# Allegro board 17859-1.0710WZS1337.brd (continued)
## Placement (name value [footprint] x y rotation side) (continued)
C6306  SCD047U25V2KX-4-GP  [C402H22]  219.71 4.17 90 top
C6307  SCD1U16V2KX-3DLGP  [C402H22]  219.71 3.39 90 top
C6308  SCD047U25V2KX-4-GP  [C402H22]  217.6 22.43 180 top
C6311  SCD22U10V2KX-2-GP  [C402H22]  204.54 21.01 90 bottom
C6312  SCD22U10V2KX-2-GP  [C402H22]  204.54 21.8 90 bottom
C6313  SCD22U10V2KX-2-GP  [C402H22]  205.76 17.78 90 bottom
C6314  SCD22U10V2KX-2-GP  [C402H22]  205.76 18.54 90 bottom
C6315  SCD22U10V2KX-2-GP  [C402H22]  205.32 15.49 90 bottom
C6316  SCD22U10V2KX-2-GP  [C402H22]  205.32 16.25 90 bottom
C6321  SC22U6D3V3MX-1-DL-GP  [C603H40]  216.28 19.18 270 top
C6322  SC22U6D3V3MX-1-DL-GP  [C603H40]  217.06 7.42 180 top
C6401  SCD1U16V2KX-3DLGP  [C402H22]  52.95 54.13 90 top
C6402  SCD1U16V2KX-3GP  [C402H22]  41.09 54.92 0 top
C6501  SCD1U16V2KX-3GP  [C402H22]  97.61 14.23 180 top
C6502  SCD1U16V2KX-3GP  [C402H22]  100.68 14.46 180 top
C6503  SCD1U16V2KX-3GP  [C402H22]  173.88 14.56 90 top
C6504  SCD1U16V2KX-3GP  [C402H22]  177.39 6.58 90 top
C7003  SCD1U25V2KX-1-DL-GP  [C402H22]  167.43 55.58 90 top
C7004  SC10U6D3V3MX-GP  [C603H38]  167.43 54.43 90 top
C7219  SC1U25V3KX-1-DLGP  [C603H36]  71.42 102.52 90 top
C7220  SC220P50V2KX-3GP  [C402H22]  72.38 105.03 0 top
C7221  SC220P50V2KX-3GP  [C402H22]  71.24 104.73 90 top
C7222  SC22U6D3V3MX-1-DL-GP  [C603H40]  67.2 94.19 0 top
C7223  SCD22U10V2KX-L1-GP  [C402H22]  74.8 98.58 0 bottom
C7224  SC2D2U10V3KX-L-GP  [C603H36]  86.83 101.52 90 bottom
C7225  SC1U10V2KX-L1-GP  [C402H22]  83.31 101.78 90 top
C7226  SC2D2U10V3KX-L-GP  [C603H36]  79.6 93.4 180 top
C7227  SC22U6D3V3MX-1-DL-GP  [C603H40]  68.47 94.19 0 top
C7228  SC10U6D3V3MX-L-GP  [C603H38]  83.74 99.98 90 top
C7229  SC10U6D3V3MX-L-GP  [C603H38]  86.91 94.49 270 top
C7230  SC2D2U10V3KX-L-GP  [C603H36]  84.32 98.2 0 top
C7231  SC22U6D3V3MX-1-DL-GP  [C603H40]  69.74 94.19 0 top
C7232  SC22U6D3V3MX-1-DL-GP  [C603H40]  70.94 94.19 0 top
C7244  SCD1U16V2KX-3DLGP  [C402H22]  83.56 100.97 90 top
C7301  SCD1U16V2KX-3DLGP  [C402H22]  31.85 71.45 90 top
C7302  SCD1U16V2KX-3DLGP  [C402H22]  31.85 72.27 90 top
C7303  SCD1U16V2KX-3DLGP  [C402H22]  23.84 67.39 180 top
C7304  SCD1U16V2KX-3DLGP  [C402H22]  23.08 67.39 180 top
C7305  SCD1U16V2KX-3DLGP  [C402H22]  21.08 66.96 180 top
C7306  SCD1U16V2KX-3DLGP  [C402H22]  20.31 66.96 180 top
C7307  SCD1U16V2KX-3DLGP  [C402H22]  26.61 66.78 180 top
C7308  SCD1U16V2KX-3DLGP  [C402H22]  28.39 65.97 180 top
C7309  SCD1U16V2KX-3DLGP  [C402H22]  27.63 65.97 180 top
C7310  SCD1U16V2KX-3DLGP  [C402H22]  30.6 65.56 180 top
C7311  SCD1U16V2KX-3DLGP  [C402H22]  29.84 65.56 180 top
C7312  SCD1U16V2KX-3DLGP  [C402H22]  24.07 65.69 180 top
C7313  SCD1U16V2KX-3DLGP  [C402H22]  24.84 65.69 180 top
C7314  SCD1U16V2KX-3DLGP  [C402H22]  25.85 66.78 180 top
C7315  SCD1U16V2KX-3DLGP  [C402H22]  29.25 69.09 0 bottom
C7316  SCD1U16V2KX-3DLGP  [C402H22]  29.43 71.33 180 bottom
C7317  SCD1U16V2KX-3DLGP  [C402H22]  18.51 71.05 270 top
C7318  SCD1U16V2KX-3DLGP  [C402H22]  30.19 71.33 180 bottom
C7319  SC10U6D3V3MX-DL-GP  [C603H36]  24.4 70.61 270 bottom
C7321  SCD1U16V2KX-3DLGP  [C402H22]  25.6 74.6 180 top
C7322  SCD1U16V2KX-3DLGP  [C402H22]  26.36 74.6 180 top
C7323  SCD1U16V2KX-3DLGP  [C402H22]  27.12 74.6 180 top
C7324  SCD1U16V2KX-3DLGP  [C402H22]  27.88 74.6 180 top
C7325  SCD1U25V2KX-1-DL-GP  [C402H22]  10.38 85.75 180 bottom
C7326  SCD1U25V2KX-1-DL-GP  [C402H22]  10.92 90.93 180 bottom
C7327  SCD1U25V2KX-1-DL-GP  [C402H22]  13.56 91.75 90 top
C7328  SCD1U25V2KX-1-DL-GP  [C402H22]  13.56 90.99 90 top
C7329  SC1U25V3KX-1-DLGP  [C603H36]  12.87 85.19 180 bottom
C7330  SC10U25V5KX-DL-GP  [C805H58]  13.28 91.47 180 bottom
C7331  SCD1U16V2KX-3DLGP  [C402H22]  28.11 77.07 180 top
C7332  SCD1U16V2KX-3DLGP  [C402H22]  27.33 77.07 180 top
C7333  SCD1U16V2KX-3DLGP  [C402H22]  24.63 76.41 180 top
C7334  SCD1U16V2KX-3DLGP  [C402H22]  25.39 76.41 180 top
C7401  SC1500P50V2KX-2GP  [C402H22]  24.58 85.78 270 bottom
C7601  SCD22U10V2KX-1GP  [C402H22]  161.56 80.7 90 top
C7602  SCD22U10V2KX-1GP  [C402H22]  161.56 79.91 90 top
C7603  SCD22U10V2KX-1GP  [C402H22]  161.57 82.33 90 top
C7604  SCD22U10V2KX-1GP  [C402H22]  161.57 81.56 90 top
C7605  SCD22U10V2KX-1GP  [C402H22]  158.65 83.74 90 top
C7606  SCD22U10V2KX-1GP  [C402H22]  158.65 84.59 90 top
C7607  SCD22U10V2KX-1GP  [C402H22]  159.3 82.19 90 top
C7608  SCD22U10V2KX-1GP  [C402H22]  159.3 82.96 90 top
C7610  SC4D7U6D3V3KX-DLGP  [C603H36]  183.28 106.91 0 bottom
C7611  SC4D7U6D3V3KX-DLGP  [C603H36]  186.38 104.57 270 bottom
C7612  SC1U10V2KX-1GP  [C402H22]  180.59 106.43 0 bottom
C7613  SC4D7U6D3V3KX-DLGP  [C603H36]  186.38 105.84 270 bottom
C7614  SC1U10V2KX-1GP  [C402H22]  178.12 85.42 225 top
C7615  SC4D7U6D3V3KX-DLGP  [C603H36]  177.79 97.79 0 bottom
C7616  SCD1U16V2KX-3GP  [C402H22]  176.98 85.45 45 top
C7620  SC4D7U6D3V3KX-DLGP  [C603H36]  178.18 89.82 225 top
C7621  SC4D7U6D3V3KX-DLGP  [C603H36]  180.49 92.97 225 top
C7622  SC1U10V2KX-1GP  [C402H22]  182.34 91.11 135 top
C7623  SC10U6D3V3MX-GP  [C603H38]  186.38 103.3 270 bottom
C7624  SC4D7U6D3V3KX-DLGP  [C603H36]  179.22 99.14 0 bottom
C7625  SC10U6D3V3MX-GP  [C603H38]  184.55 106.91 0 bottom
C7626  SC22U6D3V3MX-1-DL-GP  [C603H40]  182.01 106.91 0 bottom
C7627  SC10U6D3V3MX-GP  [C603H38]  178.66 91.14 225 top
C7628  SC22U6D3V3MX-1-DL-GP  [C603H40]  179.11 87.25 45 top
C7629  SC10U6D3V3MX-GP  [C603H38]  179.57 92.05 225 top
C7630  SC1U10V2KX-1GP  [C402H22]  181.78 91.68 135 top
C7631  SC1U10V2KX-1GP  [C402H22]  180.97 93.96 225 top
C7632  SCD1U16V2KX-3GP  [C402H22]  176.4 93.65 225 top
C7633  SC1U10V2KX-1GP  [C402H22]  176.96 94.21 225 top
C7634  SC4D7U6D3V3KX-DLGP  [C603H36]  176.91 92.1 315 top
C7801  SCD1U16V2KX-3GP  [C402H22]  187.17 95.14 225 top
C7802  SCD1U16V2KX-3GP  [C402H22]  187.7 95.69 225 top
C7805  SCD1U16V2KX-3GP  [C402H22]  186.3 88.72 315 top
C7806  SCD1U16V2KX-3GP  [C402H22]  188.31 82.15 270 top
C7807  SC1U25V3KX-1-DLGP  [C603H36]  208.1 86.21 0 bottom
C7808  SCD1U16V2KX-3GP  [C402H22]  188.31 81.37 270 top
C7809  SCD1U16V2KX-3GP  [C402H22]  197.33 74.12 45 top
C7813  SC4D7U6D3V3KX-DLGP  [C603H36]  205.53 86.21 180 bottom
C7814  SC4D7U6D3V3KX-DLGP  [C603H36]  206.8 86.21 180 bottom
C7817  SC10U6D3V3MX-GP  [C603H38]  220.54 94.77 270 bottom
C7818  SC22U6D3V3MX-1-DL-GP  [C603H40]  184.73 89.77 315 top
C7820  SC22U6D3V3MX-1-DL-GP  [C603H40]  220.54 97.36 270 bottom
C7825  SC1U25V3KX-1-DLGP  [C603H36]  220.54 96.09 90 bottom
C7826  SC1U25V3KX-1-DLGP  [C603H36]  220.47 102.95 90 bottom
C7827  SC1U25V3KX-1-DLGP  [C603H36]  201.7 104.47 180 bottom
C7828  SC1U25V3KX-1-DLGP  [C603H36]  220.46 101.67 90 bottom
C7829  SC1U25V3KX-1-DLGP  [C603H36]  203 104.47 180 bottom
C7830  SC1U25V3KX-1-DLGP  [C603H36]  220.54 93.47 90 bottom
C7831  SC1U25V3KX-1-DLGP  [C603H36]  220.29 96.34 270 top
C7832  SC22U6D3V3MX-1-DL-GP  [C603H40]  206.83 83.26 0 bottom
C7833  SC22U6D3V3MX-1-DL-GP  [C603H40]  205.56 83.26 0 bottom
C7834  SC10U6D3V3MX-GP  [C603H38]  213.14 86.44 180 bottom
C7835  SC10U6D3V3MX-GP  [C603H38]  204.37 104.47 0 bottom
C7903  SCD1U16V2KX-3GP  [C402H22]  168.02 80.83 225 bottom
C7906  SCD1U16V2KX-3GP  [C402H22]  183.66 79.17 225 top
C7907  SC18P50V2JN-1-GP  [C402H22]  185.34 63.45 90 bottom
C7908  SC18P50V2JN-1-GP  [C402H22]  183.86 63.45 270 bottom
C7909  SCD22U10V2KX-L1-GP  [C402H22]  188.06 60.71 180 bottom
C7934  SC10U6D3V3MX-GP  [C603H38]  178.61 95.1 315 top
C7935  SC22U6D3V3MX-1-DL-GP  [C603H40]  179.98 84.56 225 top
C7936  SCD1U16V2KX-3GP  [C402H22]  181.73 81.82 135 top
C7937  SCD1U16V2KX-3GP  [C402H22]  180.44 82.15 225 top
C7938  SC22U6D3V3MX-1-DL-GP  [C603H40]  183.92 94.11 225 top
C7939  SC22U6D3V3MX-1-DL-GP  [C603H40]  180.77 95.61 45 top
C8001  SC4D7U6D3V3KX-DLGP  [C603H36]  150.84 106.68 180 top
C8002  SC4D7U6D3V3KX-DLGP  [C603H36]  149.55 106.68 180 top
C8003  SC4D7U6D3V3KX-DLGP  [C603H36]  177.06 72.06 45 bottom
C8004  SC4D7U6D3V3KX-DLGP  [C603H36]  184.83 80.62 225 top
C8008  SC4D7U6D3V3KX-DLGP  [C603H36]  151.68 96.47 90 top
C8009  SC4D7U6D3V3KX-DLGP  [C603H36]  151.68 97.74 90 top
C8010  SC22U6D3V3MX-1-DL-GP  [C603H40]  151.68 99.01 90 top
C8011  SC1U10V2KX-1GP  [C402H22]  185.09 83.34 45 top
C8012  SC1U10V2KX-1GP  [C402H22]  185.42 87.45 135 top
C8013  SC1U10V2KX-1GP  [C402H22]  187.85 87.71 135 top
C8014  SC1U10V2KX-1GP  [C402H22]  184.86 87.99 135 top
C8015  SC4D7U6D3V3KX-GP  [C603H36]  160.6 88.47 135 bottom
C8016  SC4D7U6D3V3KX-GP  [C603H36]  172.26 75.75 135 bottom
C8017  SC22U6D3V3MX-1-DL-GP  [C603H40]  168.9 79.1 135 bottom
C8018  SC1U10V2KX-1GP  [C402H22]  183 83.62 315 top
C8019  SC4D7U6D3V3KX-DLGP  [C603H36]  170.58 77.42 135 bottom
C8020  SC4D7U6D3V3KX-DLGP  [C603H36]  169.74 78.26 135 bottom
C8021  SC4D7U6D3V3KX-DLGP  [C603H36]  186.1 85.63 45 top
C8022  SC4D7U6D3V3KX-DLGP  [C603H36]  185.19 84.71 45 top
C8023  SC4D7U6D3V3KX-DLGP  [C603H36]  182.77 89.11 225 top
C8024  SC4D7U6D3V3KX-DLGP  [C603H36]  181.86 88.19 225 top
C8025  SC4D7U6D3V3KX-DLGP  [C603H36]  180.95 87.28 225 top
C8026  SC4D7U6D3V3KX-DLGP  [C603H36]  171.42 76.58 135 bottom
C8028  SC1U10V2KX-1GP  [C402H22]  178.12 71.68 315 top
C8029  SCD1U16V2KX-3GP  [C402H22]  177.57 72.24 315 top
C8030  SC4D7U6D3V3KX-DLGP  [C603H36]  187.02 86.54 45 top
C8031  SC4D7U6D3V3KX-DLGP  [C603H36]  151.68 100.28 90 top
C8032  SC4D7U6D3V3KX-DLGP  [C603H36]  151.68 101.55 90 top
C8034  SCD1U16V2KX-3GP  [C402H22]  177.01 72.8 315 top
C8035  SCD1U16V2KX-3GP  [C402H22]  184.35 79.66 225 top
C8036  SC1U10V2KX-1GP  [C402H22]  187.12 80.9 45 top
C8037  SCD1U16V2KX-3DLGP  [C402H22]  187.5 76.66 315 top
C8038  SC10U6D3V3MX-DL-GP  [C603H36]  173.1 74.91 135 bottom
C8039  SC10U6D3V3MX-DL-GP  [C603H36]  166.31 79.56 90 bottom
C8040  SC10U6D3V3MX-DL-GP  [C603H36]  174.77 73.23 135 bottom
C8041  SC10U6D3V3MX-DL-GP  [C603H36]  173.93 74.07 135 bottom
C8042  SC10U6D3V3MX-DL-GP  [C603H36]  163.47 87.68 135 bottom
C8043  SC10U6D3V3MX-DL-GP  [C603H36]  161.51 87.56 135 bottom
C8044  SC10U6D3V3MX-DL-GP  [C603H36]  165.7 88.04 315 bottom
C8045  SC10U6D3V3MX-DL-GP  [C603H36]  163.6 85.93 135 bottom
C8046  SC10U6D3V3MX-DL-GP  [C603H36]  164.51 85.02 135 bottom
C8047  SC22U6D3V3MX-1-DL-GP  [C603H40]  186.51 78.95 225 top
C8048  SC4D7U6D3V3KX-GP  [C603H36]  185.24 77.73 225 top
C8089  SCD1U16V2KX-3GP  [C402H22]  186.56 80.34 45 top
C8101  SC1U10V2KX-L1-GP  [C402H22]  220.32 71.3 90 top
C8102  SC1U10V2KX-L1-GP  [C402H22]  220.32 76.51 90 top
C8103  SC1U10V2KX-L1-GP  [C402H22]  220.32 72.06 90 top
C8104  SC1U10V2KX-L1-GP  [C402H22]  206.22 64.95 90 bottom
C8105  SC1U10V2KX-L1-GP  [C402H22]  220.32 72.16 270 bottom
C8106  SC1U10V2KX-L1-GP  [C402H22]  220.32 74.53 270 bottom
C8107  SC1U10V2KX-L1-GP  [C402H22]  220.44 71.38 270 bottom
C8108  SC1U10V2KX-L1-GP  [C402H22]  220.32 73.64 90 top
C8109  SC1U10V2KX-L1-GP  [C402H22]  220.32 75.72 90 top
C8110  SC1U10V2KX-L1-GP  [C402H22]  206.22 65.71 90 bottom
C8111  SC10U6D3V3MX-GP  [C603H38]  220.32 73.33 270 bottom
C8112  SC10U6D3V3MX-GP  [C603H38]  201.03 77.29 90 bottom
C8113  SC10U6D3V3MX-GP  [C603H38]  202.92 66.2 180 bottom
C8114  SC10U6D3V3MX-GP  [C603H38]  204.08 66.2 180 bottom
C8115  SC1U10V2KX-L1-GP  [C402H22]  220.44 100.59 270 bottom
C8116  SC1U10V2KX-L1-GP  [C402H22]  220.32 72.85 90 top
C8117  SC1U10V2KX-L1-GP  [C402H22]  220.36 77.88 270 bottom
C8118  SC1U10V2KX-L1-GP  [C402H22]  213.63 66.83 0 top
C8119  SC1U10V2KX-L1-GP  [C402H22]  220.44 99.82 270 bottom
C8120  SC1U10V2KX-L1-GP  [C402H22]  205.07 66.09 180 bottom
C8121  SC1U10V2KX-L1-GP  [C402H22]  220.32 92.71 90 top
C8122  SC1U10V2KX-L1-GP  [C402H22]  219.48 79.1 135 top
C8123  SC10U6D3V3MX-GP  [C603H38]  220.32 98.81 270 bottom
C8124  SC10U6D3V3MX-GP  [C603H38]  220.32 93.75 90 top
C8125  SC10U6D3V3MX-GP  [C603H38]  220.29 74.7 90 top
C8126  SC10U6D3V3MX-GP  [C603H38]  220.34 75.57 270 bottom
C8127  SC10U6D3V3MX-GP  [C603H38]  220.34 76.84 270 bottom
C8128  SC10U6D3V3MX-GP  [C603H38]  220.32 91.67 90 top
C8129  SC10U6D3V3MX-GP  [C603H38]  220.32 90.38 90 top
C8130  SC10U6D3V3MX-GP  [C603H38]  220.32 95.05 90 top
C8131  SC1U10V2KX-L1-GP  [C402H22]  220.29 77.32 90 top
C8132  SC1U10V2KX-L1-GP  [C402H22]  220.29 78.11 90 top
C8136  SC820P50V2KX-1-DL-GP  [C402H22]  207.34 106.3 270 top
C8140  SC820P50V2KX-1-DL-GP  [C402H22]  210.08 100.03 0 top
C8141  SCD01U50V2KX-1DLGP  [C402H22]  207.87 103 0 top
C8142  SCD01U50V2KX-1DLGP  [C402H22]  210.79 64.85 90 top
C8143  SC22U6D3V3MX-1-DL-GP  [C603H40]  210.86 65.79 180 bottom
C8144  SC22U6D3V3MX-1-DL-GP  [C603H40]  212.15 65.79 180 bottom
C8145  SC22U6D3V3MX-1-DL-GP  [C603H40]  213.45 65.79 180 bottom
C8146  SC22U6D3V3MX-1-DL-GP  [C603H40]  208.13 83.26 0 bottom
C8501  SCD1U25V2KX-GP  [C402H22]  104.77 106.07 270 bottom
C8601  SC1U10V2KX-1GP  [C402H22]  172.33 97.16 180 bottom
C8602  SC1U10V2KX-1GP  [C402H22]  169.77 100.03 90 bottom
C8603  SC1U10V2KX-1GP  [C402H22]  169.77 100.79 90 bottom
C8604  SC1U10V2KX-1GP  [C402H22]  172.74 103 0 bottom
C8605  SC1500P50V2KX-2GP  [C402H22]  179.29 101.07 180 bottom
C8606  SC10U6D3V3MX-GP  [C603H38]  176.14 98.07 0 bottom
C8607  SC10U6D3V3MX-GP  [C603H38]  176.96 101.91 270 bottom
C8608  SC470P50V2KX-3DLGP  [C402H22]  177.82 99.37 270 bottom
C8630  SCD1U16V2KX-3DLGP  [C402H22]  113.53 101.15 180 top
C8631  SCD1U16V2KX-3GP  [C402H22]  149.45 84.51 180 bottom
C9106  SC10U6D3V3MX-DL-GP  [C603H36]  209.16 33.15 0 top
C9108  SCD1U16V2KX-3DLGP  [C402H22]  210.56 33.61 90 top
C9109  SC10U6D3V3MX-DL-GP  [C603H36]  207.99 39.07 180 top
C9112  SCD1U16V2KX-3DLGP  [C402H22]  206.9 39.14 180 top
C9113  SCD1U16V2KX-3DLGP  [C402H22]  198.32 32.79 270 top
CPU1  WHISKEY-LAKE-GP  [BGA1528M2446-1H52]  107.61 72.95 270 bottom
D1701  RB520S30-GP  [SOD523AKH26]  115.97 40.13 270 top
D2401  BAT54C-12-GP  [SOT-23-9H44]  24.4 38.31 90 bottom
D2402  L1SS355T1G-GP  [SOD323AKH44]  54.58 49.99 0 top
D2405  RB520S30-GP  [SOD523AKH26]  26.54 41.38 0 top
D2501  BAT54C-12-GP  [SOT-23-9H44]  211.65 19 90 top
D2502  RB751VM-40TE-17-GP  [SOD323-2513AKH36]  208.38 22.66 0 top
D2503  BAT54A-11-GP  [SOT-23-9H44]  211.17 26.11 0 top
D2601  RB551V30-GP  [SOD323AKH38]  219.3 69.73 180 bottom
D2703  BAT54C-12-GP  [SOT-23-9H44]  25.39 21.24 0 bottom
D2901  BAT54A-11-GP  [SOT-23-9H44]  17.6 16.84 90 bottom
D4001  L1SS355T1G-GP  [SOD323AKH44]  209.04 54.61 90 top
D4002  RB520S30-GP  [SOD523AKH26]  202.99 49.99 0 top
D4003  RB520S30-GP  [SOD523AKH26]  204.39 49.99 0 top
D4004  RB520S30-GP  [SOD523AKH26]  163.21 70.28 90 bottom
D4301  P6AF24A-R1-00001-GP  [D4724AKH44]  32.38 87.73 90 bottom
D4302  LBAV99LT1G-1-GP  [SOT23-2D4-312H44]  51.78 52.15 180 top
D4303  L30ESD24VC3-2-GP  [SOT23-2D4-312H60]  19.98 98.96 180 bottom
D4304  LBAV99LT1G-1-GP  [SOT23-2D4-312H44]  112.03 10.32 0 top
D4305  LBAV99LT1G-1-GP  [SOT23-2D4-312H44]  115.28 8.49 0 top
D4306  LBAV99LT1G-1-GP  [SOT23-2D4-312H44]  115.72 5.06 270 top
D4307  SMF18A-GP  [SOD123AK-2H43]  119.53 8.56 90 top
D4308  RB751V-40H-GP  [SOD323AKH38]  30.14 75.95 180 bottom
D5502  BAT54C-12-GP  [SOT-23-9H44]  38.4 77.93 90 bottom
D5503  BAT54C-12-GP  [SOT-23-9H44]  48.41 85.98 90 bottom
D5701  LBAW56LT1G-GP  [SOT23-2D4-312H44]  21.63 65.03 90 bottom
D6101  RB520S30-GP  [SOD523AKH26]  201.37 57.05 180 top
D6102  RB520S30-GP  [SOD523AKH26]  199.18 57.1 180 top
D6401  BAT54A-11-GP  [SOT-23-9H44]  20.06 89.82 180 bottom
D7001  BAT54A-7-F-2-GP  [SOT23-2D4-312H48]  217.57 58.8 180 bottom
D7203  BX310F-R1-00000-GP  [D4724AKH44]  69.13 92.41 0 bottom
D7601  BAT54A-11-GP  [SOT-23-9H44]  161.44 76.08 90 bottom
D7902  L1SS355T1G-GP  [SOD323AKH44]  175.2 68.2 180 bottom
D8601  BAT54C-12-GP  [SOT-23-9H44]  177.55 63.07 270 bottom
D8602  RB520SM-30T2R-GP  [D1608-035030AKH28]  164.46 75.77 270 bottom
DBG1  ACES-CON14-5-GP  [87212-1400N]  36.09 58.22 180 bottom
DBG3  ACES-CON6-58-GP  [50696-00601-001]  91.61 5.17 0 top
DCIN1  ETY-CON8-23-GP-U  [3703K-Q08N-03R-U]  27.31 94 0 bottom
DM1  DDR4-260P-79-GP-U  [40-42271-26001RHF-WD-U]  65.26 23.85 0 bottom
DM2  DDR4-260P-79-GP-U  [40-42271-26001RHF-WD-U]  142.26 23.85 0 bottom
EC1201  SC2D2U6D3V2MX-DL-GP  [C402H22]  57.58 20.02 0 top
EC1202  SCD1U25V2KX-1-DL-GP  [C402H22]  40.23 25.58 180 top
EC1301  SC2D2U6D3V2MX-DL-GP  [C402H22]  157.58 22.61 180 top
EC1706  SC1KP50V2KX-1DLGP  [C402H22]  138.96 75.26 180 bottom
EC1707  SCD1U16V2KX-3DLGP  [C402H22]  121.28 40.26 180 top
EC1712  SCD1U16V2KX-3DLGP  [C402H22]  115.72 45.72 270 top
EC1801  SC10P50V2JN-4DLGP  [C402H22]  123.92 46.87 270 top
EC1803  SC4D7P50V2BN-2-GP  [C402H22]  122.78 47.22 0 top
EC1804  SCD1U16V2KX-3DLGP  [C402H22]  142.11 47.5 0 top
EC1901  SC10P50V2JN-4DLGP  [C402H22]  113.1 47.25 90 top
EC1903  SC33P50V2JN-3DLGP  [C402H22]  111.63 47.25 90 top
EC2002  SC1KP50V2KX-1DLGP  [C402H22]  162.99 83.64 90 bottom
EC2201  SCD1U16V2KX-3DLGP  [C402H22]  156.13 54.54 90 top
EC2401  SCD1U16V2KX-3GP  [C402H22]  56.71 49.18 180 top
EC2701  SCD1U25V2KX-GP  [C402H22]  24.12 17.86 180 bottom
EC2702  SCD1U25V2KX-GP  [C402H22]  23.36 17.86 180 bottom
EC2703  SCD1U25V2KX-GP  [C402H22]  16.83 14.71 270 bottom
EC2704  SCD1U25V2KX-GP  [C402H22]  13.51 13.29 180 top
EC2705  SCD1U25V2KX-GP  [C402H22]  22.09 16.72 270 bottom
EC2709  SC22P50V2JN-4GP  [C402H22]  35.07 13.9 90 top
EC2710  SC22P50V2JN-4GP  [C402H22]  35.07 14.68 90 top
EC2711  SC22P50V2JN-4GP  [C402H22]  32.07 10.32 90 top
EC2901  SC1KP50V2KX-1DLGP  [C402H22]  23.72 4.83 90 top
EC2902  SC1KP50V2KX-1DLGP  [C402H22]  22.22 4.83 270 top
EC2903  SC1KP50V2KX-1DLGP  [C402H22]  25.22 4.83 270 top
EC2904  SC1KP50V2KX-1DLGP  [C402H22]  26.71 4.83 90 top
EC2905  SC100P50V2JN-3DLGP  [C402H22]  14.24 4.78 0 bottom
EC2906  SC100P50V2JN-3DLGP  [C402H22]  16.48 12.7 270 bottom
EC2907  SC100P50V2JN-3DLGP  [C402H22]  13.43 8.77 180 bottom
EC2908  SC100P50V2JN-3DLGP  [C402H22]  13.43 7.24 0 bottom
EC3513  SCD1U16V2KX-3DLGP  [C402H22]  17.95 28.53 0 top
EC4301  SC10U25V3MX-GP  [C603H40]  28.14 88.52 90 bottom
EC4302  SCD1U25V2KX-GP  [C402H22]  28.11 92.48 270 top
EC4306  SC10P50V2JN-4GP  [C402H22]  111.47 12.42 90 top
EC4307  SC1KP50V2KX-1DLGP  [C402H22]  119.37 11.43 270 top
EC4308  SCD1U50V3KX-GP  [C603H36]  119.27 10.39 270 top
EC4309  SC10P50V2JN-4GP  [C402H22]  117.49 4.04 90 top
EC4310  SC10P50V2JN-4GP  [C402H22]  115.36 10.49 90 top
EC4311  SCD1U25V2KX-GP  [C402H22]  26.16 95.02 270 top
EC4312  SC1KP50V2KX-1DLGP  [C402H22]  28.11 90.96 270 top
EC4313  SCD1U25V2KX-GP  [C402H22]  28.11 91.72 270 top
EC4534  SC2D2U25V3KX-1-GP  [C603H40]  53.11 15.22 90 top
EC5501  SC6P50V2CN-1-NL-GP  [C402H22]  50.59 87.66 180 bottom
EC5502  SC6P50V2CN-1-NL-GP  [C402H22]  51.38 87.38 180 bottom
EC5503  SC33P50V2JN-3DLGP  [C402H22]  49.63 91.87 270 top
EC5504  SC22P50V2JN-4GP  [C402H22]  48.21 89.86 270 bottom
EC5505  PUSB3F96-GP  [DFN10G2510-1H20]  55.29 87.94 180 bottom
EC6401  SCD1U16V2KX-3GP  [C402H22]  215.23 39.25 270 top
EC6402  SCD1U25V2KX-1-DL-GP  [C402H22]  11.98 93.55 90 top
EC6403  SC1KP50V2KX-1DLGP  [C402H22]  221.33 46.15 180 top
EC6404  SCD1U25V2KX-1-DL-GP  [C402H22]  12.47 94.8 0 top
EC6501  SC33P50V2JN-3GP  [C402H22]  181.53 11.2 180 top
EC6502  SC33P50V2JN-3GP  [C402H22]  181.53 13.97 180 top
EC6503  SC33P50V2JN-3GP  [C402H22]  179.17 11.25 180 top
EC6504  SC33P50V2JN-3GP  [C402H22]  173.73 10.65 270 top
EC6505  SC33P50V2JN-3GP  [C402H22]  173.73 9.88 270 top
EC6506  SC33P50V2JN-3GP  [C402H22]  176.12 17.43 270 bottom
EC6801  SC1KP50V2KX-1DLGP  [C402H22]  139.74 75.26 180 bottom
EC8901  SCD1U25V2KX-GP  [C402H22]  164.05 29.67 180 top
EC8902  SCD1U25V2KX-GP  [C402H22]  164.84 29.67 180 top
EC8903  SCD1U25V2KX-GP  [C402H22]  55.09 19.51 0 top
EC8904  SCD1U25V2KX-GP  [C402H22]  33.7 16.92 90 bottom
EC8905  SCD1U25V2KX-GP  [C402H22]  55.85 19.51 0 top
EC8906  SCD1U25V2KX-GP  [C402H22]  167.86 19.94 0 top
EC8907  SCD1U25V2KX-GP  [C402H22]  165.65 29.67 180 top
EC8908  SCD1U25V2KX-GP  [C402H22]  81.27 18.09 0 top
EC8909  SCD1U25V2KX-GP  [C402H22]  80.49 18.09 0 top
EC8910  SCD1U25V2KX-GP  [C402H22]  162.3 29.7 180 top
EC8911  SCD1U25V2KX-GP  [C402H22]  167.08 19.94 0 top
EC8912  SCD1U25V2KX-GP  [C402H22]  161.49 29.71 180 top
EC8913  SCD1U25V2KX-GP  [C402H22]  41.95 23.24 180 top
EC8914  SCD1U25V2KX-GP  [C402H22]  168.65 19.94 0 top
EC8915  SCD1U25V2KX-GP  [C402H22]  54.32 19.51 0 top
EC8917  SCD1U25V2KX-GP  [C402H22]  59.15 12.7 180 top
EC8919  SCD1U25V2KX-GP  [C402H22]  85.47 99.88 0 bottom
EC8925  SC1KP50V2KX-1DLGP  [C402H22]  57.45 12.78 180 top
EC8928  SCD1U25V2KX-GP  [C402H22]  46.48 58.27 0 top
EC8929  SC1KP50V2KX-1DLGP  [C402H22]  86.26 99.88 0 bottom
EC8933  SC1U10V2KX-1GP  [C402H22]  20.39 67.49 0 bottom
EC8934  SC1U10V2KX-1GP  [C402H22]  30.78 10.04 0 top
EC8935  SC1U10V2KX-1GP  [C402H22]  15.84 71.73 0 bottom
EC8936  SC1U10V2KX-1GP  [C402H22]  107.59 10.34 0 top
EC8937  SC1U10V2KX-1GP  [C402H22]  14.83 35.13 90 top
EC8938  SC1U10V2KX-1GP  [C402H22]  185.41 14.28 180 top
EC8939  SC1U10V2KX-1GP  [C402H22]  21.15 67.49 0 bottom
EC8947  SC1U10V2KX-1GP  [C402H22]  35.96 76.05 0 bottom
EC8948  SC1U10V2KX-1GP  [C402H22]  89.38 104.55 180 top
EC8949  SC1U10V2KX-1GP  [C402H22]  18.79 55.65 270 bottom
EC8950  SC1U10V2KX-1GP  [C402H22]  173.45 7.04 270 top
EC8951  SC1U10V2KX-1GP  [C402H22]  211.42 36.53 90 top
EC8952  SC1U10V2KX-1GP  [C402H22]  44.83 55.58 180 top
EC8953  SC1U10V2KX-1GP  [C402H22]  222.27 23.17 180 top
EC8954  SCD1U25V2KX-GP  [C402H22]  16.83 22.94 0 bottom
EC8957  SCD1U25V2KX-GP  [C402H22]  47.26 60.51 0 bottom
EC8958  SCD1U25V2KX-GP  [C402H22]  18.64 23.45 0 bottom
EC8959  SCD1U25V2KX-GP  [C402H22]  24.89 17.86 180 bottom
EC8960  SC1KP50V2KX-1DLGP  [C402H22]  22.6 17.86 180 bottom
EC8961  SCD1U25V2KX-GP  [C402H22]  173.55 74.5 315 top
EC8962  SCD1U25V2KX-GP  [C402H22]  43.71 59.64 270 bottom
EC8963  SC1KP50V2KX-1DLGP  [C402H22]  45.71 58.27 0 top
EC8965  SCD1U25V2KX-GP  [C402H22]  172.46 75.64 315 top
EC8966  SCD1U25V2KX-GP  [C402H22]  169.11 78.97 315 top
EC8967  SCD1U25V2KX-GP  [C402H22]  182.44 84.15 315 top
EC8968  SCD1U25V2KX-GP  [C402H22]  184.54 82.79 45 top
ED301  AZ5125-02S-R7G-GP  [SOT23-2D4-312H46]  108.38 94.64 180 top
ED502  PESD5V0U2BT-215-GP  [SOT23-2D4-312H44]  145.13 43.06 90 top
ED1217  AZ5123-01F-R7G-GP-U  [SOD882-10D6-1H20]  56.69 18.39 180 top
ED1302  AZ5123-01F-R7G-GP-U  [SOD882-10D6-1H20]  134.94 18.11 270 top
ED1701  AZ5125-02S-R7G-GP  [SOT23-2D4-312H46]  133.5 41.43 270 top
ED1702  AZ5125-02S-R7G-GP  [SOT23-2D4-312H46]  144.37 64.9 90 bottom
ED1703  AZ5125-02S-R7G-GP  [SOT23-2D4-312H46]  119.3 40.57 270 top
ED1704  AZ5125-02S-R7G-GP  [SOT23-2D4-312H46]  115.46 93.91 270 top
ED1801  AZ5125-02S-R7G-GP  [SOT23-2D4-312H46]  116.38 50.19 0 top
ED2907  AZ5123-01F-R7G-GP-U  [SOD882-10D6-1H20]  14.32 13.29 180 top
ED2908  AZ5123-01F-R7G-GP-U  [SOD882-10D6-1H20]  16.15 2.97 90 top
ED2909  AZ5123-01F-R7G-GP-U  [SOD882-10D6-1H20]  14.83 14.58 270 top
ED2910  AZ5123-01F-R7G-GP-U  [SOD882-10D6-1H20]  14.98 5.16 90 top
ED2911  AZ5123-01F-R7G-GP-U  [SOD882-10D6-1H20]  14.98 7.47 90 top
ED2912  AZ5123-01F-R7G-GP-U  [SOD882-10D6-1H20]  13.53 13.29 0 bottom
ED3501  PUSB3F96-GP  [DFN10G2510-1H20]  17.62 26.27 270 top
ED3502  AZC099-04S-2-GP  [SOT-6H58]  17.8 38.92 0 bottom
ED3504  PUSB3F96-GP  [DFN10G2510-1H20]  16.91 44.25 270 bottom
ED4001  PESD5V0U2BT-215-GP  [SOT23-2D4-312H44]  208.43 50.4 180 top
ED5701  PUSB3F96-GP  [DFN10G2510-1H20]  15.16 57.74 270 bottom
ED5702  PUSB3F96-GP  [DFN10G2510-1H20]  15.18 61.24 270 bottom
ED5703  PUSB3F96-GP  [DFN10G2510-1H20]  14.65 65 90 top
ED6001  PUSB3F96-GP  [DFN10G2510-1H20]  193.36 15.06 180 bottom
ED6301  L05ESDL5V0NA-4-GP  [SLP2510P8-1H22]  205.18 13.59 270 bottom
ED6401  AZ5123-01F-R7G-GP-U  [SOD882-10D6-1H20]  222.17 46.18 180 top
ED7301  PUSB3F96-GP  [DFN10G2510-1H20]  13.28 85.5 90 top
ED7302  PUSB3F96-GP  [DFN10G2510-1H20]  14.22 81.41 90 top
ED7303  AZ5315-02F-GP  [SOT883-1D0-321H20]  32.96 75.24 270 top
ED7304  AZ5315-02F-GP  [SOT883-1D0-321H20]  17.67 87.25 270 top
ED7305  AZ5315-02F-GP  [SOT883-1D0-321H20]  12.87 89.23 270 top
ED7306  AZ5315-02F-GP  [SOT883-1D0-321H20]  10.15 86.62 180 top
ED7307  AZ5123-01F-R7G-GP-U  [SOD882-10D6-1H20]  215.67 8.87 90 top
EL3501  DLM0NSN900HY2D-GP  [LD85D65-4P-1H20]  21.97 40.34 0 bottom
EL3506  DLM0NSN900HY2D-GP  [LD85D65-4P-1H20]  20.34 39.53 0 bottom
EL4301  0R5J-5-GP  [R805H24]  31.82 90.76 0 top
EL4302  0R5J-5-GP  [R805H24]  30.07 90.78 0 top
EL4303  0R5J-5-GP  [R805H24]  20.31 92.41 90 bottom
EL4304  0R5J-5-GP  [R805H24]  23.16 94.57 270 top
EL5501  DLM0NSN900HY2D-GP  [LD85D65-4P-1H20]  52.98 89 90 bottom
EL7301  DLM0NSN900HY2D-GP  [LD85D65-4P-1H20]  17.67 87.25 90 bottom
EL7302  DLM0NSN900HY2D-GP  [LD85D65-4P-1H20]  12.24 89.26 90 bottom
ER5701  150R2J-L1-GP-U  [R402H16]  16.45 62.11 180 bottom
ER5702  150R2J-L1-GP-U  [R402H16]  16.45 58.65 180 bottom
ER5703  150R2J-L1-GP-U  [R402H16]  16.45 56.87 180 bottom
ER5704  150R2J-L1-GP-U  [R402H16]  16.45 60.33 180 bottom
ER7201  0R5J-5-GP  [R805H24]  68.6 96.32 90 bottom
ER7202  0R5J-5-GP  [R805H24]  68.6 98.22 90 bottom
F5503  POLYSW-1D1A24V-GP-U  [POLYSW-4633-UH43]  41.93 95.99 270 top
F5504  POLYSW-1D1A6V-9-GP-U  [POLYSW-2114H30]  51.3 93.25 0 top
F5701  POLYSW-1D1A6V-9-GP-U  [POLYSW-2114H30]  15.23 70.06 90 bottom
F6502  POLYSW-1D1A6V-9-GP-U  [POLYSW-2114H30]  99.28 14.58 180 bottom
FAN1  ACES-CON4-29-GP  [50224-0040N-001]  220.11 64.5 270 bottom
FC1102  SC2D2U6D3V2MX-DL-GP  [C402H22]  96.8 45.63 0 top
FC1103  SC2D2U6D3V2MX-DL-GP  [C402H22]  96.01 45.63 0 top
FC1801  SC4D7P50V2BN-2-GP  [C402H22]  118.89 52.89 180 top
FC6101  SC10P50V2JN-4DLGP  [C402H22]  219.75 57.48 90 bottom
FC8901  SCD1U16V2KX-3GP  [C402H22]  209.37 43.89 180 top
FC8902  SCD1U16V2KX-3GP  [C402H22]  54.63 33.07 0 top
FC8903  SCD1U16V2KX-3GP  [C402H22]  183.56 40.59 90 bottom
FC8904  SCD1U16V2KX-3GP  [C402H22]  182.8 49.1 180 top
FC8905  SCD1U16V2KX-3GP  [C402H22]  209.52 28.55 270 top
FC8906  SCD1U16V2KX-3GP  [C402H22]  53 64.34 180 bottom
FC8907  SCD1U16V2KX-3GP  [C402H22]  208.27 45.01 270 top
FC8908  SCD1U16V2KX-3GP  [C402H22]  208.27 45.77 270 top
FC8909  SCD1U16V2KX-3GP  [C402H22]  36.54 7.57 90 bottom
FC8910  SCD1U16V2KX-3GP  [C402H22]  66.11 100.99 0 bottom
FC8911  SCD1U16V2KX-3GP  [C402H22]  155.11 54.82 270 bottom
FC8912  SCD1U16V2KX-3GP  [C402H22]  123.57 95.3 180 top
FC8913  SCD1U16V2KX-3GP  [C402H22]  124.33 95.3 180 top
FC8914  SCD1U16V2KX-3GP  [C402H22]  114.37 104.42 270 bottom
FC8915  SCD1U16V2KX-3GP  [C402H22]  148.74 55.17 270 top
FC8916  SCD1U25V2KX-1-DL-GP  [C402H22]  135.55 10.62 0 top
FC8917  SCD1U25V2KX-1-DL-GP  [C402H22]  44.95 58.27 0 top
FC8918  SCD1U25V2KX-1-DL-GP  [C402H22]  47.44 93.35 90 top
FC8919  SCD1U25V2KX-1-DL-GP  [C402H22]  134.84 94.06 90 top
FC8920  SCD1U25V2KX-1-DL-GP  [C402H22]  164.84 72.09 180 top
FC8921  SCD1U25V2KX-1-DL-GP  [C402H22]  48.05 60.51 0 bottom
FC8922  SCD1U25V2KX-1-DL-GP  [C402H22]  46.16 77.38 90 bottom
FC8923  SCD1U25V2KX-1-DL-GP  [C402H22]  124.35 95.05 0 bottom
FC8924  SCD1U25V2KX-1-DL-GP  [C402H22]  130.19 107.77 0 bottom
FC8925  SCD1U25V2KX-1-DL-GP  [C402H22]  134.21 107.32 90 top
FC8926  SCD1U25V2KX-1-DL-GP  [C402H22]  177.44 59.74 90 top
FC8927  SCD1U25V2KX-1-DL-GP  [C402H22]  194 42.88 180 top
FC8928  SCD1U25V2KX-1-DL-GP  [C402H22]  60.01 12.7 180 top
FC8929  SCD1U25V2KX-1-DL-GP  [C402H22]  152.78 15.78 180 top
FC8930  SCD1U25V2KX-1-DL-GP  [C402H22]  126.66 15.73 90 top
G1801  GAP-OPEN  [CON2O-U]  127.38 45.95 0 top
G6401  GAP-OPEN  [CON2O-U]  218.64 46.15 180 top
G6402  GAP-OPEN  [CON2O-U]  220.16 46.15 180 top
GPU1  N16S-GM-S-A2-GP  [BGA595M23H83]  184.09 84.5 45 bottom
H1  HOLE276R150-GP  [HOLE276R150]  137.21 60.85 180 bottom
H2  HOLE276R150-GP  [HOLE276R150]  76.21 85.15 180 bottom
H3  HOLE276R150-GP  [HOLE276R150]  137.21 85.15 180 bottom
H4  HOLE276R150-GP  [HOLE276R150]  76.21 60.85 180 bottom
H5  HOLE276R150-GP  [HOLE276R150]  163.86 93.88 180 bottom
H6  HOLE276R150-GP  [HOLE276R150]  192.24 103.6 180 bottom
H7  HOLE276R150-GP  [HOLE276R150]  191.31 67.47 180 bottom
H8  HOLE335R115-GP  [HOLE335R115]  158.11 105.4 0 bottom
H9  HOLE335R178-GP  [HOLE335R178]  186.26 22 180 bottom
H10  HOLE237R170-GP  [HOLE237R170]  19.61 76 0 bottom
H11  HOLE256R126-1-GP  [HOLE256R126]  32.16 4 0 bottom
H12  HOLE256R126-1-GP  [HOLE256R126]  63.11 105.5 180 bottom
H13  HOLE256R126-1-GP  [HOLE256R126]  107.71 4.5 180 bottom
H14  HOLE256R126-1-GP  [HOLE256R126]  198.96 11.8 0 bottom
H15  HOLE256R126-1-GP  [HOLE256R126]  219.86 84.5 0 bottom
H17  HOLE237R103-GP  [HOLE237R103]  7.71 79.4 180 bottom
HDD1  STM-CON12-GP  [FFSKL05007N12B]  188.61 10 180 bottom
HDMI1  SKT-HDMI23-209-GP  [SKT-HDMI23-188146-1]  2.81 67.6 90 bottom
HS1  STF237R113H86-GP  [STF237R113H86]  204.46 27.75 180 bottom
IOBD1  STAR-CON40-8-GP  [300E40-1010RA-G3]  220.73 43 270 bottom
KB1  ACES-CON30-28-GP  [196528-30041-3]  74.11 7.25 180 bottom
KB_BL1  ACES-CON4-90-GP-U  [50698-00401-W01-U]  97.91 6.05 180 bottom
L7602  HCB1608KF121T30-GP  [L1608-UH38]  180.56 104.63 270 bottom
L7801  HCB1608KF121T30-GP  [L1608-UH38]  183.86 90.63 315 top
L7901  HCB1608KF121T30-GP  [L1608-UH38]  179.06 83.64 45 top
L7902  MCB1608S181FBP-GP  [L603H38]  181.99 102.47 135 bottom
L8001  MHC1608S300QBP-GP  [L603H38]  182.62 81 135 top
LCD1  STAR-CON40-8-GP  [300E40-1010RA-G3]  47.81 95 0 bottom
LED1  LED-YW-5-GP  [LED3020-3P-19H44]  2.71 98.5 0 top
NOREF  -  []  84.61 60.95 0 top
NOREF#2  -  []  -13.29 3 0 top
NOREF#3  -  []  1.74 1.01 90 top
NOREF#4  -  []  204.37 32.75 90 top
NOREF#5  -  []  1.86 11.65 0 top
NOREF#6  -  []  133.2 92.99 90 top
NOREF#7  -  []  -8.6 18.45 0 top
NOREF#8  -  []  10.65 29.15 90 top
NOREF#9  *  [unnamed#2]  79.24 15.17 0 top
NOREF#10  -  []  182.2 64.9 90 top
NOREF#11  -  []  1.86 7.15 0 top
NOREF#12  -  []  5.34 2.51 90 top
NOREF#13  -  []  -0.27 19.98 0 top
NOREF#14  -  []  2.74 7.01 90 top
NOREF#15  -  []  5.14 11.51 90 top
NOREF#16  -  []  12.15 48.65 90 top
NOREF#17  -  [unnamed#2]  219.71 27.5 0 top
NOREF#18  -  []  2.74 7.01 90 top
NOREF#19  -  []  2.74 7.01 90 top
NOREF#20  -  []  2.74 7.01 90 top
NOREF#21  -  []  132.66 137.09 0 top
NOREF#22  -  []  4.45 37.3 90 top
NOREF#23  -  []  200.73 33.38 0 top
NOREF#24  -  []  4.46 2.65 90 top
NOREF#25  -  []  -12.47 96.62 0 top
NOREF#26  -  []  -7.89 8.17 90 top
NOREF#27  -  []  20.34 36.01 90 top
NOREF#28  -  []  -2.94 95.22 0 top
NOREF#29  -  []  18.09 23.81 90 top
NOREF#30  -  []  4.29 36.51 0 top
NOREF#31  -  []  -2.61 84.12 0 top
NOREF#32  -  []  21.79 107.02 0 top
NOREF#33  -  []  3.14 -1.9 0 top
NOREF#34  -  []  10.86 71.6 90 top
NOREF#35  -  []  1.59 12.32 0 top
NOREF#36  -  []  10.86 63.6 90 top
NOREF#37  -  [unnamed#2]  52.39 106.34 0 top
NOREF#38  -  []  205.5 36.38 90 top
NOREF#39  -  []  4.45 37.3 90 top
NOREF#40  -  []  1.86 11.65 0 top
NOREF#41  -  []  10.89 11.51 90 top
NOREF#42  *  [unnamed#2]  158.19 77.57 0 top
NOREF#43  -  []  207.81 1.36 90 top
NOREF#44  -  []  201.62 32.36 0 top
NOREF#45  -  []  85.29 62.09 0 top
NOREF#46  -  []  3.14 -1.9 90 top
NOREF#47  -  []  -3.68 26.28 0 top
NOREF#48  -  []  70.94 52.68 0 top
NOREF#49  -  []  12.15 41.65 90 top
NOREF#50  -  []  133.2 131.09 0 top
NOREF#51  -  []  1.59 12.32 0 top
NOREF#52  -  []  27.31 94 90 top
NOREF#53  -  []  2.74 7.01 0 top
NOREF#54  -  []  4.45 17.3 90 top
NOREF#55  -  [unnamed#2]  -4.01 -67.58 0 top
NOREF#56  -  []  200.24 43.78 0 top
NOREF#57  -  []  -1.8 38.34 0 top
NOREF#58  -  []  99.41 61.64 90 top
NOREF#59  -  []  -2.94 95.22 0 top
NOREF#60  -  []  200.49 37.63 90 top
NOREF#61  -  []  207.53 8.43 0 top
NOREF#62  -  []  85.29 62.09 0 top
NOREF#63  -  []  200.73 33.38 0 top
NOREF#64  -  []  200.24 38.01 90 top
NOREF#65  -  []  -2.47 53.46 0 top
NOREF#66  -  []  -9.1 -2.18 90 top
NOREF#67  -  []  -8.6 18.45 0 top
NOREF#68  -  []  78.66 59.95 0 top
NOREF#69  -  []  -2.89 3.39 90 top
NOREF#70  -  []  -2.89 3.39 0 top
NOREF#71  -  []  4.29 16.51 0 top
NOREF#72  -  []  175.5 103.28 90 top
NOREF#73  -  []  1.72 8.09 90 top
NOREF#74  -  []  10.65 41.15 90 top
NOREF#75  -  []  30.81 90.23 90 top
NOREF#76  -  []  1.86 2.65 90 top
NOREF#77  -  []  85.29 62.74 90 top
NOREF#78  -  []  -2.47 33.46 0 top
NOREF#79  -  []  2.74 7.01 90 top
NOREF#80  -  []  9.46 2.65 90 top
NOREF#81  -  []  -2.94 95.22 0 top
NOREF#82  -  []  170.75 108.05 0 top
NOREF#83  -  []  1.86 7.15 0 top
NOREF#84  -  []  -4.59 93.14 0 top
NOREF#85  -  []  -3.68 46.28 0 top
NOREF#86  -  [unnamed#2]  222.57 105.46 0 top
NOREF#87  -  []  -2.5 59.84 0 top
NOREF#88  -  []  175.51 103.28 90 top
NOREF#89  -  []  12.15 24.15 90 top
NOREF#90  -  []  182.75 58.9 90 top
NOREF#91  -  []  205.5 33.38 90 top
NOREF#92  -  []  98.51 61.64 90 top
NOREF#93  -  []  1.72 8.09 90 top
NOREF#94  -  []  5.14 11.51 90 top
NOREF#95  -  []  1.59 1.6 90 top
NOREF#96  -  []  10.86 63.6 90 top
NOREF#97  -  []  22.05 99.94 90 top
NOREF#98  -  []  9.31 63.1 90 top
NOREF#99  -  []  -2.61 84.12 0 top
NOREF#100  -  []  1.72 8.09 0 top
NOREF#101  -  []  138.65 86.45 0 top
NOREF#102  -  []  10.65 49.15 90 top
NOREF#103  -  []  212.3 1.36 90 top
NOREF#104  -  []  11.25 18.75 90 top
NOREF#105  -  []  85.29 62.74 90 top
NOREF#106  -  []  1.86 7.15 0 top
NOREF#107  -  [unnamed#2]  171.55 -108.32 180 top
NOREF#108  -  []  2.74 7.01 0 top
NOREF#109  -  []  88.56 59.95 0 top
NOREF#110  -  []  1.25 82.93 90 top
NOREF#111  -  []  10.34 2.51 90 top
NOREF#112  -  []  -2.5 59.84 90 top
NOREF#113  -  []  9.31 64.1 0 top
NOREF#114  -  []  98.34 37.92 0 top
NOREF#115  -  []  11.25 38.75 90 top
NOREF#116  -  []  170.75 108.12 0 top
NOREF#117  -  []  88.35 33.87 0 top
NOREF#118  -  []  -4.59 93.14 0 top
NOREF#119  *  [unnamed#2]  222.73 78.44 0 top
NOREF#120  -  []  21.36 -109.57 180 top
NOREF#121  -  [unnamed#2]  222.85 2.44 0 top
NOREF#122  -  []  84.61 60.95 0 top
NOREF#123  -  []  2.81 58.45 90 top
NOREF#124  -  []  2.74 2.51 90 top
NOREF#125  -  []  10.65 41.15 90 top
NOREF#126  -  []  175.52 103.28 90 top
NOREF#127  -  []  10.89 11.51 90 top
NOREF#128  -  []  5.34 2.51 90 top
NOREF#129  -  []  209.13 11.97 0 top
NOREF#130  -  []  11.25 51.55 90 top
NOREF#131  -  []  200.99 33 0 top
NOREF#132  -  []  -1.8 18.34 90 top
NOREF#133  -  []  207.81 11.16 0 top
NOREF#134  -  []  231.95 66.71 0 top
NOREF#135  -  []  1.25 82.93 90 top
NOREF#136  -  []  -2.61 84.12 0 top
NOREF#137  -  []  -4.44 17.79 0 top
NOREF#138  -  []  4.45 17.3 90 top
NOREF#139  -  []  174.16 109.48 0 top
NOREF#140  -  []  2.74 7.01 90 top
NOREF#141  *  [unnamed#2]  222.96 5.39 0 top
NOREF#142  -  []  -46.31 -37.64 0 top
NOREF#143  -  []  -4.84 65.58 0 top
NOREF#144  -  []  132.66 87 0 top
NOREF#145  -  []  205.5 33.38 90 top
NOREF#146  -  []  174.95 43.68 0 top
NOREF#147  -  []  0.86 1.05 90 top
NOREF#148  -  []  -13.29 3 0 top
NOREF#149  -  []  -7.89 8.17 90 top
NOREF#150  -  []  20.34 16.01 90 top
NOREF#151  -  []  201.19 94.13 0 top
NOREF#152  *  [unnamed#2]  4.08 106.76 0 top
NOREF#153  -  []  -5.17 34.89 270 top
NOREF#154  -  []  -12.47 96.62 0 top
NOREF#155  -  []  201.62 32.36 0 top
NOREF#156  -  []  203.95 107.57 0 top
NOREF#157  -  []  10.65 21.15 90 top
NOREF#158  -  []  2.81 58.45 90 top
NOREF#159  -  []  93.31 88.8 0 top
NOREF#160  -  []  -1.8 18.34 0 top
NOREF#161  -  []  -1.8 38.34 90 top
NOREF#162  -  []  0.34 22.15 0 top
NOREF#163  -  []  1.86 7.15 0 top
NOREF#164  -  []  22.05 109.75 0 top
NOREF#165  -  []  176.75 59.45 90 top
NOREF#166  -  []  -7.89 18.45 90 top
NOREF#167  -  []  -17.73 76.24 0 top
NOREF#168  -  []  1.72 8.09 90 top
NOREF#169  -  []  200.49 43.4 0 top
NOREF#170  -  []  99.41 61.64 90 top
NOREF#171  -  []  12.15 21.65 90 top
NOREF#172  -  []  84.4 62.74 90 top
NOREF#173  *  [unnamed#2]  -1.53 -106.01 0 top
NOREF#174  -  []  22.05 99.94 90 top
NOREF#175  -  []  4.63 3.39 90 top
NOREF#176  -  []  1.72 8.09 90 top
NOREF#177  -  []  132.66 87 90 top
NOREF#178  -  []  207.81 1.36 90 top
NOREF#179  -  []  175.5 103.28 90 top
NOREF#180  -  []  12.15 28.65 90 top
NOREF#181  -  []  133.2 64.9 0 top
NOREF#182  -  []  200.24 38.01 90 top
NOREF#183  -  []  154.75 88.04 90 top
NOREF#184  -  []  201.37 32.75 0 top
NOREF#185  -  []  1.74 1.01 90 top
NOREF#186  -  []  200.24 43.78 0 top
NOREF#187  -  []  -7.34 22.15 0 top
NOREF#188  -  []  -0.57 20.43 0 top
NOREF#189  -  []  -4.59 93.14 0 top
NOREF#190  -  []  2.81 58.45 90 top
NOREF#191  -  []  201.37 32.75 0 top
NOREF#192  -  []  0.34 22.15 0 top
NOREF#193  -  [unnamed#2]  229.36 103.91 0 top
NOREF#194  -  []  205.5 36.38 90 top
NOREF#195  -  []  204.37 32.75 90 top
NOREF#196  -  [unnamed#2]  14.41 99.3 0 top
NOREF#197  -  []  201.37 32.75 0 top
NOREF#198  -  []  3.14 -1.9 90 top
NOREF#199  -  []  133.7 64.9 0 top
NOREF#200  -  []  1.25 82.93 90 top
NOREF#201  *  [unnamed#2]  225.56 -108.96 0 top
NOREF#202  -  []  2.81 76.75 90 top
NOREF#203  -  []  9.31 72.1 90 top
NOREF#204  -  []  154.75 87.54 90 top
NOREF#205  -  []  11.25 31.55 90 top
NOREF#206  -  []  -12.47 96.62 0 top
NOREF#207  -  []  10.26 60.35 90 top
NOREF#208  -  []  -2.93 74.9 0 top
NOREF#209  -  []  -7.34 22.15 0 top
NOREF#210  -  []  201.37 32.75 0 top
NOREF#211  -  []  23.37 110.56 0 top
NOREF#212  -  []  18.09 43.81 90 top
NOREF#213  -  []  12.15 44.15 90 top
NOREF#214  -  []  -4.44 17.79 0 top
NOREF#215  -  []  2.81 58.45 90 top
NOREF#216  -  []  10.65 21.15 90 top
NOREF#217  -  []  1.59 1.6 90 top
NOREF#218  -  []  174.16 109.48 0 top
NOREF#219  -  []  -7.89 18.45 90 top
NOREF#220  -  []  86.48 45.95 0 top
NOREF#221  -  []  138.65 136.54 0 top
NOREF#222  -  []  93.05 53.5 180 bottom
NOREF#223  -  []  197.52 96.39 180 bottom
NOREF#224  *  [unnamed#2]  79.24 15.17 180 bottom
NOREF#225  *  [unnamed#2]  -1.53 -106.01 180 bottom
NOREF#226  *  [unnamed#2]  4.08 106.76 180 bottom
NOREF#227  -  []  82.21 53.93 180 bottom
NOREF#228  *  [unnamed#2]  158.19 77.57 180 bottom
NOREF#229  *  [unnamed#2]  222.96 5.39 180 bottom
NOREF#230  *  [unnamed#2]  222.73 78.44 180 bottom
NOREF#231  *  [unnamed#2]  225.56 -108.96 180 bottom
NOREF#232  -  []  209.69 36.82 180 bottom
NOREF#233  -  []  -5.22 -0.13 90 bottom
PC1001  SC22U6D3V3MX-1-DL-GP  [C603H40]  62.15 66.65 180 top
PC1002  SC22U6D3V3MX-1-DL-GP  [C603H40]  64.61 84.03 180 top
PC1003  SC22U6D3V3MX-1-DL-GP  [C603H40]  107.03 77.5 270 top
PC1004  SC22U6D3V3MX-1-DL-GP  [C603H40]  105.2 68.76 270 top
PC1005  SC22U6D3V3MX-1-DL-GP  [C603H40]  67.96 90.68 180 top
PC1006  SC22U6D3V3MX-1-DL-GP  [C603H40]  102.41 68.15 270 top
PC1007  SC22U6D3V3MX-1-DL-GP  [C603H40]  100.76 72.37 270 top
PC1008  SC22U6D3V3MX-1-DL-GP  [C603H40]  65.6 86.79 0 bottom
PC1009  SC22U6D3V3MX-1-DL-GP  [C603H40]  65.48 88.19 270 top
PC1010  SC22U6D3V3MX-1-DL-GP  [C603H40]  110.08 76.23 90 top
PC1011  SC22U6D3V3MX-1-DL-GP  [C603H40]  107.03 73.69 270 top
PC1012  SC22U6D3V3MX-1-DL-GP  [C603H40]  63.34 84.03 180 top
PC1013  SC22U6D3V3MX-1-DL-GP  [C603H40]  107.03 74.96 270 top
PC1014  SC22U6D3V3MX-1-DL-GP  [C603H40]  103.88 73.59 90 top
PC1015  SC22U6D3V3MX-1-DL-GP  [C603H40]  100.76 73.64 270 top
PC1016  SC22U6D3V3MX-1-DL-GP  [C603H40]  103.88 74.88 90 top
PC1017  SC22U6D3V3MX-1-DL-GP  [C603H40]  103.88 76.18 90 top
PC1018  SC22U6D3V3MX-1-DL-GP  [C603H40]  65.91 84.03 180 top
PC1019  SC22U6D3V3MX-1-DL-GP  [C603H40]  70.5 90.68 180 top
PC1020  SC22U6D3V3MX-1-DL-GP  [C603H40]  107.03 76.23 270 top
PC1021  SC22U6D3V3MX-1-DL-GP  [C603H40]  103.88 77.45 90 top
PC1022  SC22U6D3V3MX-1-DL-GP  [C603H40]  66.67 90.68 180 top
PC1023  SC22U6D3V3MX-1-DL-GP  [C603H40]  67.28 72.32 0 top
PC1024  SC22U6D3V3MX-1-DL-GP  [C603H40]  103.88 72.32 90 top
PC1025  SC22U6D3V3MX-1-DL-GP  [C603H40]  107.03 72.42 270 top
PC1026  SC22U6D3V3MX-1-DL-GP  [C603H40]  107.92 68.71 270 top
PC1027  SC22U6D3V3MX-1-DL-GP  [C603H40]  67.23 84.03 180 top
PC1028  SC22U6D3V3MX-1-DL-GP  [C603H40]  69.23 90.68 180 top
PC1029  SC22U6D3V3MX-1-DL-GP  [C603H40]  68.5 84.03 180 top
PC1030  SC22U6D3V3MX-1-DL-GP  [C603H40]  110.46 68.71 270 top
PC1031  SC22U6D3V3MX-1-DL-GP  [C603H40]  110.08 77.5 90 top
PC1032  SC22U6D3V3MX-1-DL-GP  [C603H40]  100.76 71.1 270 top
PC1034  SC22U6D3V3MX-1-DL-GP  [C603H40]  65.48 86.9 270 top
PC1036  SC22U6D3V3MX-1-DL-GP  [C603H40]  110.08 71.15 90 top
PC1037  SC22U6D3V3MX-1-DL-GP  [C603H40]  82.7 72.49 0 top
PC1038  SC22U6D3V3MX-1-DL-GP  [C603H40]  63.42 66.65 180 top
PC1039  SC22U6D3V3MX-1-DL-GP  [C603H40]  64.69 66.65 180 top
PC1040  SC22U6D3V3MX-1-DL-GP  [C603H40]  98.19 70.64 0 top
PC1041  SC22U6D3V3MX-1-DL-GP  [C603H40]  67.96 56.97 180 bottom
PC1042  SC22U6D3V3MX-1-DL-GP  [C603H40]  94.25 76.91 0 top
PC1043  SC22U6D3V3MX-1-DL-GP  [C603H40]  66.67 56.97 180 bottom
PC1044  SC22U6D3V3MX-1-DL-GP  [C603H40]  92.98 76.91 0 top
PC1045  SC22U6D3V3MX-1-DL-GP  [C603H40]  81.12 77.7 180 top
PC1046  SC22U6D3V3MX-1-DL-GP  [C603H40]  60.85 66.65 180 top
PC1047  SC22U6D3V3MX-1-DL-GP  [C603H40]  96.79 73.84 180 top
PC1048  SC22U6D3V3MX-1-DL-GP  [C603H40]  80.31 72.49 0 top
PC1049  SC22U6D3V3MX-1-DL-GP  [C603H40]  69.26 56.97 180 bottom
PC1050  SC22U6D3V3MX-1-DL-GP  [C603H40]  64.1 56.97 180 bottom
PC1051  SC22U6D3V3MX-1-DL-GP  [C603H40]  95.52 73.84 180 top
PC1052  SC22U6D3V3MX-1-DL-GP  [C603H40]  61.54 56.97 0 top
PC1053  SC22U6D3V3MX-1-DL-GP  [C603H40]  81.5 72.49 0 top
PC1054  SC22U6D3V3MX-1-DL-GP  [C603H40]  67.94 68.51 270 top
PC1055  SC22U6D3V3MX-1-DL-GP  [C603H40]  91.71 76.91 0 top
PC1056  SC22U6D3V3MX-1-DL-GP  [C603H40]  91.71 73.84 180 top
PC1057  SC22U6D3V3MX-1-DL-GP  [C603H40]  89.88 75.95 90 top
PC1058  SC22U6D3V3MX-1-DL-GP  [C603H40]  89.88 74.07 90 top
PC1059  SC22U6D3V3MX-1-DL-GP  [C603H40]  96.9 70.64 0 top
PC1060  SC22U6D3V3MX-1-DL-GP  [C603H40]  95.52 76.91 0 top
PC1061  SC22U6D3V3MX-1-DL-GP  [C603H40]  67.94 67.21 270 top
PC1062  SC22U6D3V3MX-1-DL-GP  [C603H40]  92.98 73.84 180 top
PC1063  SC22U6D3V3MX-1-DL-GP  [C603H40]  95.6 70.61 0 top
PC1064  SC22U6D3V3MX-1-DL-GP  [C603H40]  94.25 73.84 180 top
PC1065  SC22U6D3V3MX-1-DL-GP  [C603H40]  65.98 66.65 180 top
PC1066  SC22U6D3V3MX-1-DL-GP  [C603H40]  87.04 71.63 0 top
PC1067  SC22U6D3V3MX-1-DL-GP  [C603H40]  85.74 71.63 0 top
PC1068  SC22U6D3V3MX-1-DL-GP  [C603H40]  98.09 73.84 180 top
PC1069  SC22U6D3V3MX-1-DL-GP  [C603H40]  83.1 80.11 270 top
PC1070  SC22U6D3V3MX-1-DL-GP  [C603H40]  65.37 56.97 180 bottom
PC1071  SC22U6D3V3MX-1-DL-GP  [C603H40]  112.67 76.66 0 top
PC1072  SC22U6D3V3MX-1-DL-GP  [C603H40]  105.79 102.72 0 bottom
PC1073  SC22U6D3V3MX-1-DL-GP  [C603H40]  104.49 97.67 180 bottom
PC1074  SC22U6D3V3MX-1-DL-GP  [C603H40]  106.27 97.67 0 top
PC1075  SC22U6D3V3MX-1-DL-GP  [C603H40]  105.76 97.67 180 bottom
PC1076  SC22U6D3V3MX-1-DL-GP  [C603H40]  104.46 102.72 0 bottom
PC1077  SC22U6D3V3MX-1-DL-GP  [C603H40]  112.44 71.83 270 top
PC1078  SC22U6D3V3MX-1-DL-GP  [C603H40]  105 97.67 0 top
PC1079  SC22U6D3V3MX-1-DL-GP  [C603H40]  103.88 71.02 90 top
PC1080  SC22U6D3V3MX-1-DL-GP  [C603H40]  107.03 71.15 270 top
PC1081  SC22U6D3V3MX-1-DL-GP  [C603H40]  110.08 73.69 90 top
PC1082  SC22U6D3V3MX-1-DL-GP  [C603H40]  110.08 72.42 90 top
PC1083  SC22U6D3V3MX-1-DL-GP  [C603H40]  68.55 72.32 0 top
PC1084  SC22U6D3V3MX-1-DL-GP  [C603H40]  110.08 74.96 90 top
PC4401  SC10U25V5KX-DL-GP  [C805H58]  151.86 15.34 270 bottom
PC4402  SC10U25V3MX-GP  [C603H40]  148.48 5.67 0 top
PC4403  SC10U25V5KX-DL-GP  [C805H58]  152.52 9.55 270 bottom
PC4404  SC10U25V5KX-DL-GP  [C805H58]  149.88 7.52 180 bottom
PC4405  SC10U25V3MX-GP  [C603H40]  150.44 6.35 90 top
PC4406  SCD1U25V2KX-1-DL-GP  [C402H22]  136.37 15.29 180 top
PC4407  SC10U25V3MX-GP  [C603H40]  133.14 14.99 180 top
PC4408  SC10U25V3MX-GP  [C603H40]  131.87 14.99 180 top
PC4409  SC10U25V3MX-GP  [C603H40]  131.87 14.99 0 bottom
PC4410  SC10U25V3MX-GP  [C603H40]  134.41 14.99 0 bottom
PC4411  SC10U25V3MX-GP  [C603H40]  130.6 14.99 0 bottom
PC4412  SC10U25V5KX-DL-GP  [C805H58]  135.96 15.6 0 bottom
PC4413  SC10U25V3MX-GP  [C603H40]  128.04 14.99 180 top
PC4414  SC10U25V3MX-GP  [C603H40]  134.41 14.99 180 top
PC4415  SCD1U50V3KX-DL-GP  [C603H35]  164.26 8.79 0 top
PC4416  SC1U50V3KX-1-GP  [C603H36]  166.08 8.77 270 top
PC4417  SC1U50V3KX-1-GP  [C603H36]  166.39 10.04 270 top
PC4418  SC10U25V3MX-GP  [C603H40]  133.14 14.99 0 bottom
PC4419  SC1U50V3KX-1-GP  [C603H36]  164.46 6.48 90 top
PC4420  SCD022U16V2KX-3DLGP  [C402H22]  157.75 4.65 180 top
PC4421  SC4D7U6D3V3KX-DLGP  [C603H36]  164.38 15.6 0 bottom
PC4422  SC4D7U6D3V3KX-DLGP  [C603H36]  161.82 6.48 90 top
PC4423  SCD22U25V3KX-DL-GP  [C603H36]  159.99 16.46 0 bottom
PC4424  SC1U50V3KX-1-GP  [C603H36]  157.8 15.75 180 bottom
PC4425  SCD1U25V2KX-1-DL-GP  [C402H22]  156.97 14.56 270 top
PC4426  SC1U50V3KX-1-GP  [C603H36]  156.53 15.75 180 bottom
PC4427  SC10U25V3MX-GP  [C603H40]  133.88 3.97 90 top
PC4429  SC4700P50V2KX-1DLGP  [C402H22]  130.4 6.48 90 bottom
PC4430  SC10P50V2JN-4DLGP  [C402H22]  157.78 6.81 180 bottom
PC4431  SCD033U25V2KX-GP  [C402H22]  155.34 8.87 180 top
PC4432  SC1KP50V2KX-1DLGP  [C402H22]  154.88 14.23 180 top
PC4433  SC470P50V2KX-3DLGP  [C402H22]  155.85 9.98 90 bottom
PC4434  SC10U25V3MX-GP  [C603H40]  130.6 14.99 180 top
PC4435  SC1KP50V2KX-1DLGP  [C402H22]  140.48 5.46 270 top
PC4436  SCD47U25V3KX-1-DL-GP  [C603H36]  165.88 14.76 90 top
PC4437  SC10U25V3MX-GP  [C603H40]  129.31 14.99 180 top
PC4438  SCD1U16V2KX-3DLGP  [C402H22]  170.63 14.35 90 top
PC4439  SC1U50V3KX-1-GP  [C603H36]  158.92 16.28 0 top
PC4440  SC1U50V3KX-1-GP  [C603H36]  156.2 12.7 270 bottom
PC4441  SC2200P50V2KX-2DLGP  [C402H22]  155.87 8.41 90 bottom
PC4442  SC1KP50V2KX-1DLGP  [C402H22]  163.27 15.14 0 top
PC4443  SC2200P50V2KX-2GP  [C402H22]  131.13 12.58 270 top
PC4445  SC1KP50V2KX-1DLGP  [C402H22]  155.16 14.71 270 bottom
PC4446  SCD1U16V2KX-3DLGP  [C402H22]  97.76 11.36 270 top
PC4447  SC10U25V3MX-GP  [C603H40]  118.94 4.68 180 top
PC4501  SCD1U25V2KX-GP  [C402H22]  199.23 45.75 180 top
PC4502  SC10U25V3MX-GP  [C603H40]  195.57 43.36 270 top
PC4503  SC10U25V3MX-GP  [C603H40]  195.98 44.63 270 top
PC4504  SC10U25V3MX-GP  [C603H40]  200.53 45.75 180 top
PC4505  SC10U25V3MX-GP  [C603H40]  52.47 8.49 90 bottom
PC4506  SCD1U25V2KX-GP  [C402H22]  190.88 43.44 180 top
PC4507  SC4D7U6D3V3KX-DLGP  [C603H36]  193.31 49.79 270 top
PC4508  SCD1U25V2KX-GP  [C402H22]  199.49 52.45 270 top
PC4509  SC22U6D3V3MX-1-DL-GP  [C603H40]  187.22 48.24 180 top
PC4510  SC22U6D3V3MX-1-DL-GP  [C603H40]  187.13 43.46 0 top
PC4511  SC22U6D3V3MX-1-DL-GP  [C603H40]  188.4 43.46 0 top
PC4512  SC22U6D3V3MX-1-DL-GP  [C603H40]  185.85 43.46 0 top
PC4513  SCD1U25V2KX-1-DL-GP  [C402H22]  186.1 48.26 180 top
PC4514  SC22U6D3V3MX-1-DL-GP  [C603H40]  40.99 3.41 0 top
PC4515  SC22U6D3V3MX-1-DL-GP  [C603H40]  40.43 8.21 180 top
PC4516  SC22U6D3V3MX-1-DL-GP  [C603H40]  42.97 8.21 180 top
PC4517  SC22U6D3V3MX-1-DL-GP  [C603H40]  41.7 8.21 180 top
PC4518  SCD1U16V2KX-3GP  [C402H22]  39.41 8.21 180 top
PC4519  SC10U25V5KX-GP  [C805H56]  57.12 5.51 180 bottom
PC4520  SC4D7U6D3V3KX-DLGP  [C603H36]  50.08 3.13 90 bottom
PC4521  SCD1U25V2KX-GP  [C402H22]  49.45 7.57 180 bottom
PC4522  SCD1U25V2KX-GP  [C402H22]  55.82 6.2 180 bottom
PC4523  SC10U25V3MX-GP  [C603H40]  52.47 8.46 270 top
PC4524  SC2D2U10V3KX-1GP  [C603H36]  51.73 5.54 180 top
PC4525  SC22U6D3V3MX-1-DL-GP  [C603H40]  188.49 48.24 180 top
PC4526  SC1KP50V2KX-1DLGP  [C402H22]  53.51 2.24 180 bottom
PC4527  SC22U6D3V3MX-1-DL-GP  [C603H40]  43.53 3.41 0 top
PC4529  SC22U6D3V3MX-1-DL-GP  [C603H40]  42.26 3.41 0 top
PC4530  SCD1U25V2KX-GP  [C402H22]  55.8 2.49 0 top
PC4531  SCD1U25V2KX-GP  [C402H22]  55.04 2.49 0 top
PC4532  SCD1U25V2KX-GP  [C402H22]  197.15 51.64 90 top
PC4533  SC1KP50V2KX-1DLGP  [C402H22]  195.7 51.06 180 top
PC4601  SC2200P50V2KX-2DLGP  [C402H22]  46.15 69.7 270 bottom
PC4602  SCD1U25V2KX-1-DL-GP  [C402H22]  41.73 61.65 0 top
PC4603  SCD1U25V2KX-1-DL-GP  [C402H22]  47.52 62.59 0 bottom
PC4604  SC330P50V2KX-3-DL-GP  [C402H22]  36.16 61.19 90 top
PC4605  SCD047U25V2KX-4-GP  [C402H22]  45.87 65.13 0 bottom
PC4606  SCD22U25V3KX-DL-GP  [C603H36]  42.74 61.22 180 bottom
PC4607  SC1U10V2KX-1DLGP  [C402H22]  41.37 61.37 270 bottom
PC4608  SCD022U16V2KX-3DLGP  [C402H22]  46.63 65.13 180 bottom
PC4609  SCD01U25V2KX-3DLGP  [C402H22]  31.41 70.41 270 bottom
PC4610  SC33P50V2JN-3DLGP  [C402H22]  38.25 65.66 270 top
PC4611  SC2200P50V2KX-2DLGP  [C402H22]  44.72 62.99 270 bottom
PC4612  SC2200P50V2KX-2DLGP  [C402H22]  32.48 60.66 180 bottom
PC4613  SCD01U25V2KX-3DLGP  [C402H22]  41.07 65.64 270 top
PC4614  SC330P50V2KX-3-DL-GP  [C402H22]  33.47 63.27 90 bottom
PC4615  SCD01U25V2KX-3DLGP  [C402H22]  33.47 64.04 270 bottom
PC4616  SC1KP50V2KX-1DLGP  [C402H22]  46.17 66.55 270 bottom
PC4617  SC1KP50V2KX-1DLGP  [C402H22]  47.82 68.23 270 bottom
PC4618  SC470P50V2KX-3DLGP  [C402H22]  33.85 65.31 0 bottom
PC4619  SC1KP50V2KX-1DLGP  [C402H22]  32 66.02 270 bottom
PC4620  SCD01U25V2KX-3DLGP  [C402H22]  49.02 67.44 270 bottom
PC4621  SC680P50V2KX-2DLGP  [C402H22]  42.36 66.6 180 top
PC4622  SCD01U25V2KX-3DLGP  [C402H22]  34.67 66.83 0 bottom
PC4623  SC2200P50V2KX-2DLGP  [C402H22]  36.09 70.39 180 bottom
PC4624  SC33P50V2JN-3DLGP  [C402H22]  46.15 68.94 270 bottom
PC4625  SCD022U16V2KX-3DLGP  [C402H22]  34.82 71.66 90 bottom
PC4626  SCD022U16V2KX-3DLGP  [C402H22]  32.91 74.22 90 bottom
PC4628  SCD033U25V2KX-GP  [C402H22]  31.41 71.94 270 bottom
PC4629  SC330P50V2KX-3-DL-GP  [C402H22]  41.07 67.77 90 top
PC4630  SCD1U25V2KX-1-DL-GP  [C402H22]  34.31 68.61 0 bottom
PC4631  SCD1U25V2KX-1-DL-GP  [C402H22]  46.65 72.7 270 bottom
PC4632  SC2200P50V2KX-2DLGP  [C402H22]  43.76 70.59 180 bottom
PC4633  SCD1U25V2KX-1-DL-GP  [C402H22]  33.17 69.55 90 bottom
PC4634  SCD1U25V2KX-1-DL-GP  [C402H22]  43.96 72.39 90 bottom
PC4635  SCD01U25V2KX-3DLGP  [C402H22]  43.99 74.68 90 bottom
PC4637  SCD01U25V2KX-3DLGP  [C402H22]  42.24 72.61 90 bottom
PC4638  SC330P50V2KX-3-DL-GP  [C402H22]  37.54 75.72 270 bottom
PC4639  SC33P50V2JN-3DLGP  [C402H22]  37.94 73.71 0 bottom
PC4640  SC2200P50V2KX-2DLGP  [C402H22]  38.83 75.29 0 bottom
PC4641  SC330P50V2KX-3-DL-GP  [C402H22]  39.57 73.69 0 bottom
PC4642  SC1KP50V2KX-1DLGP  [C402H22]  42.24 73.39 90 bottom
PC4643  SC1KP50V2KX-1DLGP  [C402H22]  40.7 74.32 270 bottom
PC4644  SCD01U25V2KX-3DLGP  [C402H22]  40.52 75.11 90 bottom
PC4651  SC1KP50V2KX-1DLGP  [C402H22]  31.69 60.66 180 bottom
PC4652  SCD022U16V2KX-3DLGP  [C402H22]  43.99 73.92 90 bottom
PC4653  SCD047U25V2KX-4-GP  [C402H22]  31.41 71.17 270 bottom
PC4701  SC10U25V3MX-GP  [C603H40]  54.22 58.35 270 bottom
